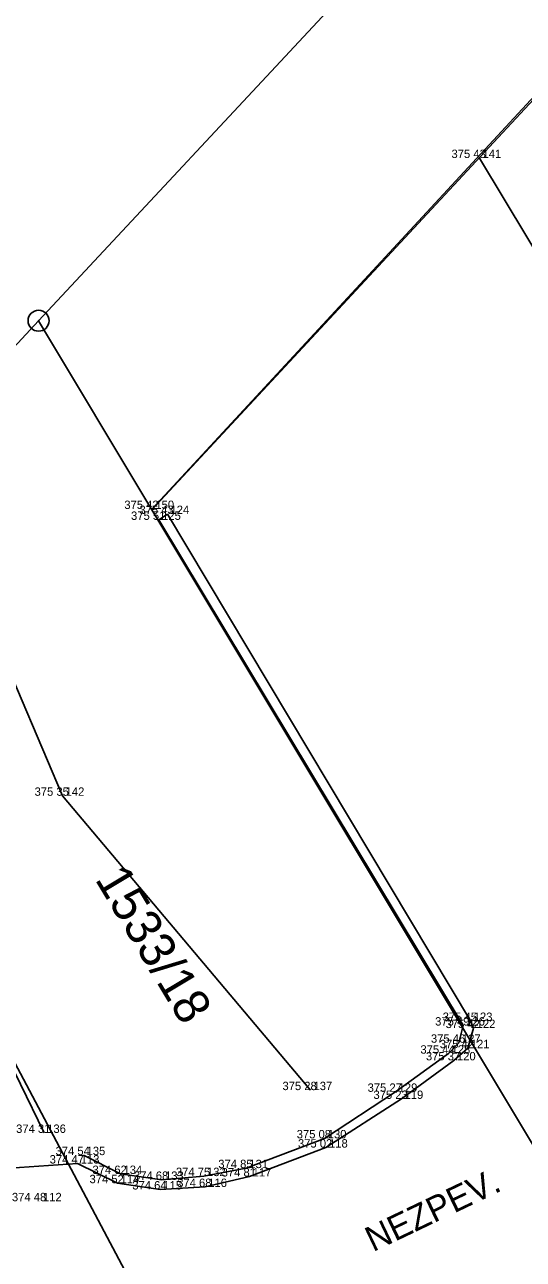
# Model space of a CAD drawing. Extents: x -601196 to -600262, y -1082523 to -1081922.
# Drawn here: x -600464.23 to -600452.34, y -1082316.78 to -1082287.34 of the extents above; entities that cross this region are included whole.
import ezdxf

# ---------------------------------------------------------------- set-up
doc = ezdxf.new("R2010")
doc.units = 0
for name, color, linetype in [('Vrstva 1', 7, 'Continuous'), ('Vrstva 11', 7, 'Continuous'), ('Vrstva 14', 7, 'Continuous'), ('Vrstva 2', 7, 'Continuous'), ('Vrstva 3', 7, 'Continuous'), ('Vrstva 40', 7, 'Continuous'), ('Vrstva 47', 7, 'Continuous'), ('Vrstva 7', 7, 'Continuous')]:
    doc.layers.add(name, color=color, linetype=linetype)

msp = doc.modelspace()

# ---------------------------------------------------------------- linework, layer by layer
at = {"layer": 'Vrstva 1'}
for p, q in [((-600453.39, -1082290.52), (-600453.39, -1082290.52)), ((-600461.19, -1082298.89), (-600461.19, -1082298.89)), ((-600461.03, -1082299.15), (-600461.03, -1082299.15)), ((-600460.83, -1082299.01), (-600460.83, -1082299.01)), ((-600463.33, -1082305.73), (-600463.33, -1082305.73)), ((-600453.78, -1082311.21), (-600453.78, -1082311.21)), ((-600453.6, -1082311.1), (-600453.6, -1082311.1)), ((-600453.53, -1082311.27), (-600453.53, -1082311.27)), ((-600453.88, -1082311.62), (-600453.88, -1082311.62)), ((-600454.13, -1082311.88), (-600454.13, -1082311.88)), ((-600453.67, -1082311.75), (-600453.67, -1082311.75)), ((-600454, -1082312.04), (-600454, -1082312.04)), ((-600457.42, -1082312.75), (-600457.42, -1082312.75)), ((-600455.39, -1082312.79), (-600455.39, -1082312.79)), ((-600455.25, -1082312.96), (-600455.25, -1082312.96)), ((-600463.77, -1082313.77), (-600463.77, -1082313.77)), ((-600457.08, -1082313.9), (-600457.08, -1082313.9)), ((-600457.05, -1082314.12), (-600457.05, -1082314.12)), ((-600462.97, -1082314.5), (-600462.97, -1082314.5)), ((-600462.83, -1082314.3), (-600462.83, -1082314.3)), ((-600461.95, -1082314.75), (-600461.95, -1082314.75)), ((-600459.96, -1082314.8), (-600459.96, -1082314.8)), ((-600458.95, -1082314.61), (-600458.95, -1082314.61)), ((-600458.87, -1082314.81), (-600458.87, -1082314.81)), ((-600462.02, -1082314.97), (-600462.02, -1082314.97)), ((-600461, -1082315.12), (-600461, -1082315.12)), ((-600460.96, -1082314.89), (-600460.96, -1082314.89)), ((-600459.93, -1082315.06), (-600459.93, -1082315.06)), ((-600463.87, -1082315.4), (-600463.87, -1082315.4))]:
    msp.add_line(p, q, dxfattribs=at)
at = {"layer": 'Vrstva 11'}
for p, q in [((-600460.83, -1082299.01), (-600461.03, -1082299.15)), ((-600461.03, -1082299.15), (-600453.78, -1082311.21)), ((-600453.6, -1082311.1), (-600460.83, -1082299.01)), ((-600453.6, -1082311.1), (-600460.83, -1082299.01)), ((-600453.78, -1082311.21), (-600453.88, -1082311.62)), ((-600453.67, -1082311.75), (-600453.53, -1082311.27)), ((-600453.67, -1082311.75), (-600453.53, -1082311.27)), ((-600453.53, -1082311.27), (-600453.6, -1082311.1)), ((-600453.53, -1082311.27), (-600453.6, -1082311.1)), ((-600453.88, -1082311.62), (-600454.13, -1082311.88)), ((-600454.13, -1082311.88), (-600455.39, -1082312.79)), ((-600454, -1082312.04), (-600453.67, -1082311.75)), ((-600454, -1082312.04), (-600453.67, -1082311.75)), ((-600455.25, -1082312.96), (-600454, -1082312.04)), ((-600455.25, -1082312.96), (-600454, -1082312.04)), ((-600455.39, -1082312.79), (-600457.08, -1082313.9)), ((-600457.05, -1082314.12), (-600455.25, -1082312.96)), ((-600457.05, -1082314.12), (-600455.25, -1082312.96)), ((-600457.08, -1082313.9), (-600458.95, -1082314.61)), ((-600458.87, -1082314.81), (-600457.05, -1082314.12)), ((-600458.87, -1082314.81), (-600457.05, -1082314.12)), ((-600464.82, -1082314.63), (-600462.97, -1082314.5)), ((-600462.97, -1082314.5), (-600462.02, -1082314.97)), ((-600461.95, -1082314.75), (-600462.83, -1082314.3)), ((-600460.96, -1082314.89), (-600461.95, -1082314.75)), ((-600459.96, -1082314.8), (-600460.96, -1082314.89)), ((-600458.95, -1082314.61), (-600459.96, -1082314.8)), ((-600459.93, -1082315.06), (-600458.87, -1082314.81)), ((-600459.93, -1082315.06), (-600458.87, -1082314.81)), ((-600462.02, -1082314.97), (-600461, -1082315.12)), ((-600461, -1082315.12), (-600459.93, -1082315.06)), ((-600461, -1082315.12), (-600459.93, -1082315.06))]:
    msp.add_line(p, q, dxfattribs=at)
at = {"layer": 'Vrstva 14'}
for p, q in [((-600463.33, -1082305.73), (-600472.01, -1082285.33)), ((-600457.42, -1082312.75), (-600463.33, -1082305.73)), ((-600463.77, -1082313.77), (-600467.15, -1082306.83))]:
    msp.add_line(p, q, dxfattribs=at)
at = {"layer": 'Vrstva 47'}
for p, q in [((-600463.9, -1082294.4), (-600439.85, -1082268.6)), ((-600461.2, -1082298.91), (-600436.69, -1082272.55)), ((-600470.25, -1082301.21), (-600463.9, -1082294.4)), ((-600461.2, -1082298.91), (-600463.9, -1082294.4)), ((-600450.81, -1082316.24), (-600461.2, -1082298.91)), ((-600458.32, -1082323.68), (-600470.25, -1082301.21))]:
    msp.add_line(p, q, dxfattribs=at)
for radius in [0.25, 0.005]:
    msp.add_circle((-600463.9, -1082294.4), radius, dxfattribs=at)
at = {"layer": 'Vrstva 7'}
for p, q in [((-600461.19, -1082298.89), (-600448.88, -1082285.58)), ((-600444.11, -1082306), (-600453.39, -1082290.52))]:
    msp.add_line(p, q, dxfattribs=at)

# ---------------------------------------------------------------- texts
at = {"layer": 'Vrstva 2'}
for s, p in [(' 141', (-600453.39, -1082290.52)), (' 150', (-600461.19, -1082298.89)), (' 125', (-600461.03, -1082299.15)), (' 124', (-600460.83, -1082299.01)), (' 142', (-600463.33, -1082305.73)), (' 126', (-600453.78, -1082311.21)), (' 123', (-600453.6, -1082311.1)), (' 122', (-600453.53, -1082311.27)), (' 127', (-600453.88, -1082311.62)), (' 121', (-600453.67, -1082311.75)), (' 128', (-600454.13, -1082311.88)), (' 120', (-600454, -1082312.04)), (' 137', (-600457.42, -1082312.75)), (' 129', (-600455.39, -1082312.79)), (' 119', (-600455.25, -1082312.96)), (' 136', (-600463.77, -1082313.77)), (' 130', (-600457.08, -1082313.9)), (' 118', (-600457.05, -1082314.12)), (' 135', (-600462.83, -1082314.3)), (' 113', (-600462.97, -1082314.5)), (' 134', (-600461.95, -1082314.75)), (' 131', (-600458.95, -1082314.61)), (' 114', (-600462.02, -1082314.97)), (' 133', (-600460.96, -1082314.89)), (' 132', (-600459.96, -1082314.8)), (' 116', (-600459.93, -1082315.06)), (' 117', (-600458.87, -1082314.81)), (' 115', (-600461, -1082315.12)), (' 112', (-600463.87, -1082315.4))]:
    msp.add_text(s, height=0.2, dxfattribs=at).set_placement(p)
at = {"layer": 'Vrstva 3'}
for s, p in [('375 43 ', (-600454.056, -1082290.52)), ('375 42 ', (-600461.856, -1082298.89)), ('375 51 ', (-600461.696, -1082299.15)), ('375 43 ', (-600461.496, -1082299.01)), ('375 35 ', (-600463.996, -1082305.73)), ('375 49 ', (-600454.446, -1082311.21)), ('375 45 ', (-600454.266, -1082311.1)), ('375 42 ', (-600454.196, -1082311.27)), ('375 46 ', (-600454.546, -1082311.62)), ('375 42 ', (-600454.336, -1082311.75)), ('375 44 ', (-600454.796, -1082311.88)), ('375 37 ', (-600454.666, -1082312.04)), ('375 28 ', (-600458.086, -1082312.75)), ('375 27 ', (-600456.056, -1082312.79)), ('375 23 ', (-600455.916, -1082312.96)), ('374 31 ', (-600464.436, -1082313.77)), ('375 08 ', (-600457.746, -1082313.9)), ('375 02 ', (-600457.716, -1082314.12)), ('374 54 ', (-600463.496, -1082314.3)), ('374 47 ', (-600463.636, -1082314.5)), ('374 62 ', (-600462.616, -1082314.75)), ('374 85 ', (-600459.616, -1082314.61)), ('374 52 ', (-600462.686, -1082314.97)), ('374 68 ', (-600461.626, -1082314.89)), ('374 75 ', (-600460.626, -1082314.8)), ('374 68 ', (-600460.596, -1082315.06)), ('374 81 ', (-600459.536, -1082314.81)), ('374 64 ', (-600461.666, -1082315.12)), ('374 48 ', (-600464.536, -1082315.4))]:
    msp.add_text(s, height=0.2, dxfattribs=at).set_placement(p)
at = {"layer": 'Vrstva 40'}
msp.add_text('NEZPEV.', height=0.6, rotation=25.56, dxfattribs=at).set_placement((-600455.926, -1082316.617))
at = {"layer": 'Vrstva 47'}
msp.add_text('1533/18', height=0.85, rotation=300.9443, dxfattribs=at).set_placement((-600462.57, -1082307.717))

doc.saveas('drawing.dxf')
